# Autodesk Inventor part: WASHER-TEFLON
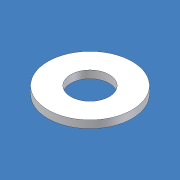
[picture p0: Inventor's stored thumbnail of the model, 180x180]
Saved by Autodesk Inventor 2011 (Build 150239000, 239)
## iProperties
Created: 2007-10
Part Number: WASHER-TEFLON
Document SubType Name: Modeling
Material: Delrin, White
Density: 1.42 g/cm^3
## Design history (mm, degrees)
feature "Base1"
body "Solid1"
